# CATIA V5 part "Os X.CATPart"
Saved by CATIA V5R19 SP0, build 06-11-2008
Part number: Os X
Bounding box of the stored display mesh (mm): x -580.734 to 86.882, y -10 to 710, z 0 to 156.298
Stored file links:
  E:\Podręcznik\catia\Machine\Os X.CATPart
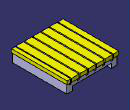
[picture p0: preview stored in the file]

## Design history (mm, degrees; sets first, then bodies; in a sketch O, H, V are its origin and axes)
Body1 (main body)
  Sketch1 on zx-plane, origin (0, 0, 0), H (-1, 0, 0), V (0, 0, 1)
    line L1 (-80.7041, 110) -> (569.2959, 110)
    line L2 (569.2959, 110) -> (569.2959, 0)
    line L3 (569.2959, 0) -> (494.2959, 0)
    line L4 (-80.7041, 0) -> (-80.7041, 110)
    point P3 (569.2959, 0)
    point P4 (-80.7041, 0)
    axis line L5 (244.2959, 418.9985) -> (244.2959, -90.8499)
    line L6 (-5.7041, 56.5607) -> (494.2959, 56.5607)
    line L7 (494.2959, 56.5607) -> (494.2959, 0)
    line L8 (-5.7041, 0) -> (-5.7041, 56.5607)
    line L9 (-5.7041, 0) -> (-80.7041, 0)
    length L2 = 110
    distance L5 L2 = 325
    length L6 = 500
    distance L8 L4 = 75
    distance P3 P4 = 650
    horizontal: L1 H, L3 H, L6 H, L9 H
    vertical: L2 V, L4 V, L5 V, L7 V, L8 V
    coincidence: P3 H, L3 L9
  Pad1: profile Sketch1, direction (0, 1, 0), length 700
  Sketch2 on end face of Pad1, origin (0, 700, 0), H (-1, 0, 0), V (0, 0, 1)
    line L1 (-24.8553, 82.2878) -> (-49.8553, 82.2878)
    line L2 (-49.8553, 114.672) -> (-24.8553, 114.672)
    line L3 (-24.8553, 114.672) -> (-24.8553, 82.2878)
    line L4 (-49.8553, 82.2878) -> (-49.8553, 114.672)
    line L5 (83.3302, 82.2878) -> (58.3302, 82.2878)
    line L6 (58.3302, 114.672) -> (83.3302, 114.672)
    line L7 (83.3302, 114.672) -> (83.3302, 82.2878)
    line L8 (58.3302, 82.2878) -> (58.3302, 114.672)
    line L9 (191.5157, 82.2878) -> (166.5157, 82.2878)
    line L10 (166.5157, 114.672) -> (191.5157, 114.672)
    line L11 (191.5157, 114.672) -> (191.5157, 82.2878)
    line L12 (166.5157, 82.2878) -> (166.5157, 114.672)
    line L13 (299.7011, 82.2878) -> (274.7011, 82.2878)
    line L14 (274.7011, 114.672) -> (299.7011, 114.672)
    line L15 (299.7011, 114.672) -> (299.7011, 82.2878)
    line L16 (274.7011, 82.2878) -> (274.7011, 114.672)
    line L17 (407.8866, 82.2878) -> (382.8866, 82.2878)
    line L18 (382.8866, 114.672) -> (407.8866, 114.672)
    line L19 (407.8866, 114.672) -> (407.8866, 82.2878)
    line L20 (382.8866, 82.2878) -> (382.8866, 114.672)
    line L21 (516.0721, 82.2878) -> (491.0721, 82.2878)
    line L22 (491.0721, 114.672) -> (516.0721, 114.672)
    line L23 (516.0721, 114.672) -> (516.0721, 82.2878)
    line L24 (491.0721, 82.2878) -> (491.0721, 114.672)
    length L1 = 25
  Pocket1: profile Sketch2, direction (0, -1, 0), through (limit type 3)
Body2
  Plane1: type Offset, Offset 10, RefPlane end face of Pad1, reversed
  Sketch3 on Plane1, origin (0, 710, 0), H (1, 0, 0), V (0, 0, 1)
    line L1 (28.0417, 111.2978) -> (-66.9561, 111.2978)
    line L2 (-66.9561, 156.2978) -> (28.0417, 156.2978)
    line L3 (-66.9561, 111.2978) -> (-66.9561, 156.2978)
    line L4 (28.0417, 156.2978) -> (28.0417, 111.2978)
    line L5 (-80.4773, 111.2978) -> (-175.4752, 111.2978)
    line L6 (-175.4752, 111.2978) -> (-175.4752, 156.2978)
    line L7 (-175.4752, 156.2978) -> (-80.4773, 156.2978)
    line L8 (-80.4773, 156.2978) -> (-80.4773, 111.2978)
    line L9 (-188.9964, 111.2978) -> (-283.9942, 111.2978)
    line L10 (-283.9942, 111.2978) -> (-283.9942, 156.2978)
    line L11 (-283.9942, 156.2978) -> (-188.9964, 156.2978)
    line L12 (-188.9964, 156.2978) -> (-188.9964, 111.2978)
    line L13 (-297.5154, 111.2978) -> (-392.5132, 111.2978)
    line L14 (-392.5132, 111.2978) -> (-392.5132, 156.2978)
    line L15 (-392.5132, 156.2978) -> (-297.5154, 156.2978)
    line L16 (-297.5154, 156.2978) -> (-297.5154, 111.2978)
    line L17 (-406.0345, 111.2978) -> (-501.0323, 111.2978)
    line L18 (-501.0323, 111.2978) -> (-501.0323, 156.2978)
    line L19 (-501.0323, 156.2978) -> (-406.0345, 156.2978)
    line L20 (-406.0345, 156.2978) -> (-406.0345, 111.2978)
    line L21 (-512.7367, 111.2978) -> (-580.7335, 111.2979)
    line L22 (-580.7335, 111.2979) -> (-580.7335, 156.2979)
    line L23 (-580.7335, 156.2979) -> (-512.7367, 156.2978)
    line L24 (-512.7367, 156.2978) -> (-512.7367, 111.2978)
    line L25 (86.8821, 111.2978) -> (38.8041, 111.2978)
    line L26 (38.8041, 111.2978) -> (38.8041, 156.2978)
    line L27 (38.8041, 156.2978) -> (86.8821, 156.2978)
    line L28 (86.8821, 156.2978) -> (86.8821, 111.2978)
  Pad2: profile Sketch3, direction (0, -1, 0), length 720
